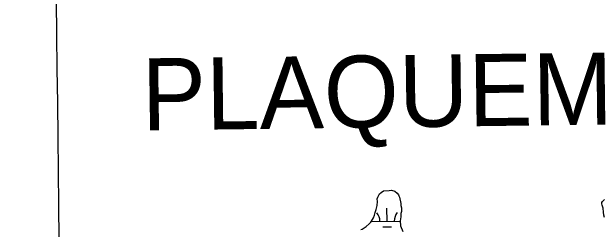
# Model space of a CAD drawing. Extents: x 3702978 to 3741108, y 397120 to 422907.
# Drawn here: x 3709641 to 3711285, y 409594 to 410197 of the extents above; entities that cross this region are included whole.
import ezdxf

# ---------------------------------------------------------------- set-up
doc = ezdxf.new("R2010")
doc.units = 0
for name, color, linetype in [('V-GRID-MAJR', 7, 'Continuous'), ('V-TOPO-GNAM-IDEN', 7, 'Continuous'), ('V-TOPO-SHOR', 7, 'Continuous'), ('V-WETL-SWMP', 7, 'Continuous')]:
    doc.layers.add(name, color=color, linetype=linetype)

msp = doc.modelspace()

# ---------------------------------------------------------------- linework, layer by layer
at = {"layer": 'V-GRID-MAJR'}
msp.add_spline([(3709855.178, 402559.365), (3709783.788, 408618.69), (3709712.386, 414679.078), (3709640.983, 420739.47), (3709640.971, 420740.528)], degree=3, dxfattribs=at)
at = {"layer": 'V-TOPO-SHOR'}
for points in [[(3710609.978, 409593.443), (3710613.372, 409594.185), (3710624.831, 409601.206), (3710632.872, 409608.846), (3710637.555, 409613.701), (3710639.55, 409616.463), (3710644.841, 409625.417), (3710647.431, 409632.96), (3710649.341, 409640.49), (3710651.919, 409648.714), (3710655.13, 409659.676), (3710656.296, 409670.6), (3710655.481, 409678.082), (3710656.758, 409682.875), (3710662.036, 409692.511), (3710666.063, 409695.991), (3710672.802, 409700.201), (3710688.447, 409701.844), (3710695.259, 409701.967), (3710704.165, 409699.401), (3710711.075, 409694.073), (3710713.886, 409689.353), (3710715.297, 409686.652), (3710716.733, 409682.589), (3710720.445, 409665.619), (3710721.237, 409659.5), (3710722.709, 409653.393), (3710722.212, 409643.162), (3710720.947, 409637.687), (3710720.437, 409628.137), (3710719.27, 409617.212), (3710718.65, 409613.794), (3710720.135, 409607.006), (3710720.196, 409603.599), (3710725.927, 409588.028)], [(3711286.055, 409626.231), (3711284.57, 409633.019), (3711283.06, 409641.17), (3711282.171, 409652.739), (3711279.299, 409660.865), (3711278.557, 409664.26), (3711279.177, 409667.678), (3711280.491, 409670.428), (3711283.155, 409673.883), (3711285.843, 409675.976)]]:
    msp.add_lwpolyline(points, dxfattribs=at)
at = {"layer": 'V-WETL-SWMP'}
for p, q in [((3710682.679, 409616.258), (3710682.232, 409652.255)), ((3710639.01, 409615.716), (3710719.179, 409616.711)), ((3710670.871, 409600.679), (3710694.87, 409600.977))]:
    msp.add_line(p, q, dxfattribs=at)
for points in [[(3710609.978, 409593.443), (3710613.372, 409594.185), (3710624.831, 409601.206), (3710632.872, 409608.846), (3710637.555, 409613.701), (3710639.55, 409616.463), (3710644.841, 409625.417), (3710647.431, 409632.96), (3710649.341, 409640.49), (3710651.919, 409648.714), (3710655.13, 409659.676), (3710656.296, 409670.6), (3710655.481, 409678.082), (3710656.758, 409682.875), (3710662.036, 409692.511), (3710666.063, 409695.991), (3710672.802, 409700.201), (3710688.447, 409701.844), (3710695.259, 409701.967), (3710704.165, 409699.401), (3710711.075, 409694.073), (3710713.886, 409689.353), (3710715.297, 409686.652), (3710716.733, 409682.589), (3710720.445, 409665.619), (3710721.237, 409659.5), (3710722.709, 409653.393), (3710722.212, 409643.162), (3710720.947, 409637.687), (3710720.437, 409628.137), (3710719.27, 409617.212), (3710718.65, 409613.794), (3710720.135, 409607.006), (3710720.196, 409603.599), (3710725.927, 409588.028)], [(3711286.055, 409626.231), (3711284.57, 409633.019), (3711283.06, 409641.17), (3711282.171, 409652.739), (3711279.299, 409660.865), (3711278.557, 409664.26), (3711279.177, 409667.678), (3711280.491, 409670.428), (3711283.155, 409673.883), (3711285.843, 409675.976)]]:
    msp.add_lwpolyline(points, dxfattribs=at)
for centre, start, end in [((3710627.434, 409616.047), 359.939883, 41.483542), ((3710737.912, 409617.419), 139.93988, 181.483539)]:
    msp.add_arc(centre, 35.246, start, end, dxfattribs=at)

# ---------------------------------------------------------------- texts
at = {"layer": 'V-TOPO-GNAM-IDEN'}
msp.add_text('PLAQUEMINES', height=199.9996, rotation=0.727268, dxfattribs=at).set_placement((3710002.724, 409868.041))

doc.saveas('drawing.dxf')
